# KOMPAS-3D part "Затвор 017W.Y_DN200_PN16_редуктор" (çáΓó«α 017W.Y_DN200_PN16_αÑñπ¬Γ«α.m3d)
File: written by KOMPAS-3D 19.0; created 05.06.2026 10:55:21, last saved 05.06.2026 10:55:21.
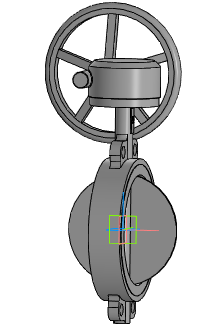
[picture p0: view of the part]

Document properties: Автор: Энергия; Полное имя файла: ..\..\..\3d для проектировщиков\x.x Тип 017W.Y(S) Затвор дисковый поворотный межфланцевый\Затвор 017W.Y(S)_DN50-DN1200_редуктор\Затвор 017W.Y_DN200_PN16_редуктор.a3d

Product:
- Part/product: Затвор 017W.Y_DN200_PN16_редуктор
    Масса: 25.5895

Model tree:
1. Операция без истории:1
